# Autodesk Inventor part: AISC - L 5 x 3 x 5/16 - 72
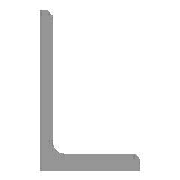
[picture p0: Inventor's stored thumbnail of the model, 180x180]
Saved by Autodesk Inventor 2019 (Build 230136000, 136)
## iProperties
Created: 2019-01
Part Number: AISC - L 5 x 3 x 5/16 - 72
Material: Steel, Mild
Description: Angle Steel
Document SubType Name: Modeling
Standard: ANSI
Designer: ElizabethC
Standards Organization: ANSI
Language: en-US
Size Designation: L 5 x 3 x 5/16
Categories: <MemberInstance><Categories><Category DisplayName="Structural Shapes" InternalName="089c4875-fa83-4c05-b084-43b9cc11f5ed" Mnemonic="GRDR"><CategoryParameter Dis
Stock Number: L 5 x 3 x 5/16
Mass: 21446.1 g
Surface Area: 6954.6 cm^2
Volume: 2731.98 cm^3
Density: 7.85 g/cm^3
Appearance: Semi-Polished
IsCustomPart: 1
_CCFamilyMember: 39
_CCFamilyDisplayName: ANSI L (Unequal angles) - Angle Steel — Sizes in parentheses have been withdrawn
_FrameMemberDoc: Frame Member File
_Version: 15.0.0
_GetPNFromCC: 1
Author: ElizabethC
G_L: 72.000 in
G_W: 3.000 in
G_H: 5.000 in
+C7612AE9-03D0-406D-AB52-40E6B7CC26CE+CUTDETAIL1: Miter 45.00 deg
+1D6AAB70-836E-4B69-B8B5-54A6666A190B+CUTDETAIL2: Miter 45.00 deg
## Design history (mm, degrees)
node "Start plane"
node "End plane"
sketch "Sketch"
  geometry: L1 (70.612, 7.95)-(19.126, 7.95); L2 (0, 0)-(76.2, 0); L3 (76.2, 0)-(76.2, 2.362); L4 (-7.041, 0)-(21.538, 0); L5 (7.95, 19.126)-(7.95, 121.412); L6 (0, 127)-(0, 0); L7 (2.362, 127)-(0, 127); L8 (0, -8.041)-(0, 34.538); L9 (0, 155.397)-(0, -35.281) reference; L10 (-23.921, 0)-(94.237, 0) reference; A1 r 11.176 centre (19.126, 19.126) between (7.95, 19.126) and (19.126, 7.95); A2 r 5.588 centre (70.612, 2.362) between (76.2, 2.362) and (70.612, 7.95); A3 r 5.588 centre (2.362, 121.412) between (7.95, 121.412) and (2.362, 127); 3 further points
  constraints: 16 end point, 6 point on circle, 6 point on line, 6 tangent, 3 centre point, 2 collinear, 2 parallel, 1 equal radius
  dimensions: "d12" = 7.9502 distance between parallel lines of L5 L6 (= G_T); "d13" = 127 distance of L6.start L2.start (= G_H); "d14" = 76.2 distance of L2.start L2.end (= G_W); "d15" = 0 distance between parallel lines of L4 L2 (computed from ex); "d16" = 7.9502 distance between parallel lines of L2 L1 (= G_T); "d17" = 0 distance between parallel lines of L8 L6 (computed from ey); "d18" = 11.176 radius of A1 (= G_IR); "d19" = 5.588 radius of A2 (= G_ER)
extrude "Body" new body sketch "Sketch" stored distance "d4" = 1828.8 (= G_L); taper "d5" = 0 deg
node "Driven Length"
  sketch "Sketch3"
    geometry: L1 (0, 0)-(10, 0) reference
    constraints: 2 end point, 1 horizontal
  workplane "Work Plane3"
  sketch "Sketch4"
    geometry: L1 (-2, 0)-(12, 0) reference; L2 (-2, 1828.8)-(12, 1828.8) reference
    dimensions: "d23" = 1828.8 distance between parallel lines of L1 L2 (derived)
workplane "Work Plane4"
split "Split1"
workplane "Work Plane5"
split "Split2"
body "Solid1"
other parameters: "G_W" = 76.2 [user parameter; used in 1 equation term], "G_H" = 127 [user parameter; used in 1 equation term], "G_T" = 7.9502 [user parameter; used in 2 equation terms], "G_ER" = 5.588 [user parameter; used in 1 equation term], "G_IR" = 11.176 [user parameter; used in 1 equation term], "G_L" = 1828.8 (= d23) [user parameter; used in 1 equation term], "ex" = 0 [user parameter; used in 1 equation term], "ey" = 0 [user parameter; used in 1 equation term], "G_OFFSET_START" = 0 [user parameter; used in 1 equation term], "G_OFFSET_END" = 0 [user parameter; used in 1 equation term], "d20" = 0 (computed from G_OFFSET_START), "d21" = 1828.8 (= G_OFFSET_END + B_L), "B_L" = 1828.8 [user parameter; used in 1 equation term], "d22" = 90 deg, "MAS" = 1.22029 [user parameter]
